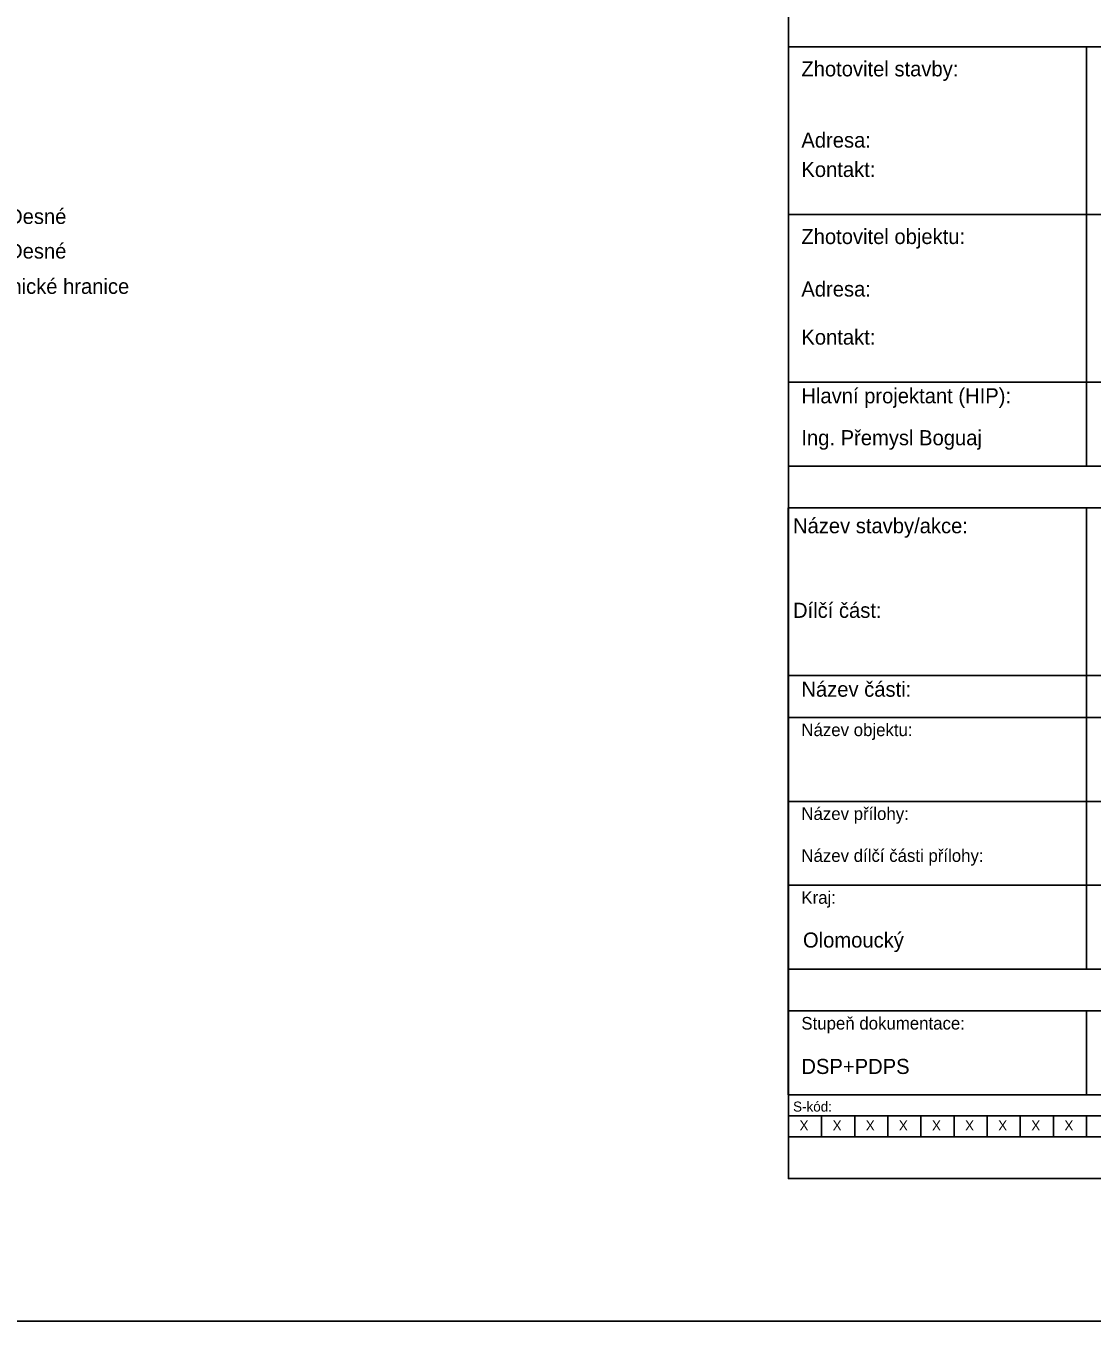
# Model space of a CAD drawing. Extents: x -558358 to -557517, y -1073785 to -1073189.
# Drawn here: x -557797.5 to -557670.3, y -1073784.1 to -1073629.6 of the extents above; entities that cross this region are included whole.
import ezdxf

# ---------------------------------------------------------------- set-up
doc = ezdxf.new("R2010")
doc.units = 0
for name, color, linetype in [('Rozpiska_pole_1', 7, 'Continuous'), ('Rozpiska_pole_6', 7, 'Continuous'), ('Rozpiska_pole_7', 7, 'Continuous'), ('Rozpiska_pole_8', 7, 'Continuous'), ('Vrstva 1', 7, 'Continuous')]:
    doc.layers.add(name, color=color, linetype=linetype)

# ---------------------------------------------------------------- blocks, each defined once
blk = doc.blocks.new('_U1')
at = {"layer": 'Rozpiska_pole_8'}
for p, q in [((-4.55, 0.25), (-4.55, -0.25)), ((-2.575, 0.25), (-2.575, -0.25)), ((-0.205, 0.25), (-0.205, -0.25)), ((3.35, 0.25), (3.35, -0.25)), ((4.535, 0.25), (4.535, -0.25)), ((6.905, 0.25), (6.905, -0.25)), ((8.5, 0), (-8.5, 0)), ((-8.105, 0), (-8.105, -0.25)), ((-7.71, 0), (-7.71, -0.25)), ((-7.315, 0), (-7.315, -0.25)), ((-6.92, 0), (-6.92, -0.25)), ((-6.525, 0), (-6.525, -0.25)), ((-6.13, 0), (-6.13, -0.25)), ((-5.735, 0), (-5.735, -0.25)), ((-5.34, 0), (-5.34, -0.25)), ((-4.945, 0), (-4.945, -0.25)), ((-4.155, 0), (-4.155, -0.25)), ((-3.76, 0), (-3.76, -0.25)), ((-3.365, 0), (-3.365, -0.25)), ((-2.97, 0), (-2.97, -0.25)), ((-2.18, 0), (-2.18, -0.25)), ((-1.785, 0), (-1.785, -0.25)), ((-1.39, 0), (-1.39, -0.25)), ((-0.995, 0), (-0.995, -0.25)), ((-0.6, 0), (-0.6, -0.25)), ((0.19, 0), (0.19, -0.25)), ((0.585, 0), (0.585, -0.25)), ((0.98, 0), (0.98, -0.25)), ((1.375, 0), (1.375, -0.25)), ((1.77, 0), (1.77, -0.25)), ((2.165, 0), (2.165, -0.25)), ((2.56, 0), (2.56, -0.25)), ((2.955, 0), (2.955, -0.25)), ((3.745, 0), (3.745, -0.25)), ((4.14, 0), (4.14, -0.25)), ((4.93, 0), (4.93, -0.25)), ((5.325, 0), (5.325, -0.25)), ((5.72, 0), (5.72, -0.25)), ((6.115, 0), (6.115, -0.25)), ((6.51, 0), (6.51, -0.25)), ((7.3, 0), (7.3, -0.25)), ((7.695, 0), (7.695, -0.25)), ((8.09, 0), (8.09, -0.25))]:
    blk.add_line(p, q, dxfattribs=at)
blk.add_lwpolyline([(-8.5, 0.25), (8.5, 0.25), (8.5, -0.25), (-8.5, -0.25)], close=True, dxfattribs=at)
for s, p in [('S-kód:', (-8.445, 0.049)), ('Stupeň dokumentace:', (-4.497, 0.065)), ('Část:', (-2.534, 0.034)), ('Objekt:', (-0.157, 0.07)), ('Podobjekt:', (3.364, 0.07)), ('Příloha:', (4.607, 0.049)), ('Revize:', (6.936, 0.056))]:
    blk.add_text(s, height=0.12, dxfattribs=at).set_placement(p)

msp = doc.modelspace()

# ---------------------------------------------------------------- linework, layer by layer
at = {"layer": 'Rozpiska_pole_1'}
msp.add_lwpolyline([(-557706.53, -1073507.09), (-557536.53, -1073507.09), (-557536.53, -1073767.09), (-557706.53, -1073767.09)], close=True, dxfattribs=at)
at = {"layer": 'Rozpiska_pole_6'}
for p, q in [((-557670.98, -1073682.09), (-557670.98, -1073632.09)), ((-557706.53, -1073652.09), (-557536.53, -1073652.09)), ((-557706.53, -1073672.09), (-557536.53, -1073672.09))]:
    msp.add_line(p, q, dxfattribs=at)
msp.add_lwpolyline([(-557706.53, -1073632.09), (-557536.53, -1073632.09), (-557536.53, -1073682.09), (-557706.53, -1073682.09)], close=True, dxfattribs=at)
at = {"layer": 'Rozpiska_pole_7'}
for p, q in [((-557670.98, -1073742.09), (-557670.98, -1073687.09)), ((-557706.53, -1073707.09), (-557576.18, -1073707.09)), ((-557706.53, -1073712.09), (-557576.18, -1073712.09)), ((-557706.53, -1073722.09), (-557576.18, -1073722.09)), ((-557706.53, -1073732.09), (-557576.18, -1073732.09)), ((-557706.53, -1073742.09), (-557576.18, -1073742.09)), ((-557706.53, -1073747.09), (-557576.18, -1073747.09)), ((-557670.98, -1073757.09), (-557670.98, -1073747.09))]:
    msp.add_line(p, q, dxfattribs=at)
msp.add_lwpolyline([(-557706.55, -1073687.09), (-557536.55, -1073687.09), (-557536.55, -1073757.09), (-557706.55, -1073757.09)], close=True, dxfattribs=at)
at = {"layer": 'Vrstva 1'}
msp.add_line((-557516.53, -1073784.09), (-558357.53, -1073784.09), dxfattribs=at)

# ---------------------------------------------------------------- block references
at = {"layer": 'Rozpiska_pole_8', "xscale": 10, "yscale": 10}
msp.add_blockref('_U1', (-557621.53, -1073759.59), dxfattribs=at)

# ---------------------------------------------------------------- texts
at = {"layer": 'Rozpiska_pole_6'}
for s, p in [('Zhotovitel stavby:', (-557704.99, -1073635.61)), ('Adresa:', (-557704.99, -1073644.11)), ('Kontakt:', (-557704.99, -1073647.61)), ('hranice pozemku Svazek obcí údolí Desné', (-557838.3, -1073653.21)), ('Zhotovitel objektu:', (-557704.99, -1073655.61)), ('hranice pozemku Svazek obcí údolí Desné', (-557838.3, -1073657.34)), ('předpokládaná změna průběhu vlastnické hranice', (-557838.3, -1073661.55)), ('Adresa:', (-557704.99, -1073661.87)), ('Kontakt:', (-557704.99, -1073667.61)), ('Hlavní projektant (HIP):', (-557704.99, -1073674.61)), ('Ing. Přemysl Boguaj', (-557704.99, -1073679.61))]:
    msp.add_text(s, height=1.8, dxfattribs=at).set_placement(p)
at = {"layer": 'Rozpiska_pole_7'}
for s, height, p in [('Název stavby/akce:', 1.8, (-557705.99, -1073690.11)), ('Dílčí část:', 1.8, (-557705.99, -1073700.2)), ('Název části:', 1.8, (-557704.99, -1073709.61)), ('Název objektu:', 1.5, (-557704.99, -1073714.31)), ('Název přílohy:', 1.5, (-557704.99, -1073724.31)), ('Název dílčí části přílohy:', 1.5, (-557704.99, -1073729.31)), ('Kraj:', 1.5, (-557704.99, -1073734.31)), ('Olomoucký', 1.8, (-557704.8, -1073739.53)), ('Stupeň dokumentace:', 1.5, (-557704.99, -1073749.31)), ('DSP+PDPS', 1.8, (-557704.99, -1073754.61))]:
    msp.add_text(s, height=height, dxfattribs=at).set_placement(p)
at = {"layer": 'Rozpiska_pole_8'}
for p in [(-557705.21, -1073761.35), (-557701.26, -1073761.35), (-557697.31, -1073761.35), (-557693.36, -1073761.35), (-557689.41, -1073761.35), (-557685.46, -1073761.35), (-557681.51, -1073761.35), (-557677.56, -1073761.35), (-557673.61, -1073761.35)]:
    msp.add_text('X', height=1.2, dxfattribs=at).set_placement(p)

doc.saveas('drawing.dxf')
